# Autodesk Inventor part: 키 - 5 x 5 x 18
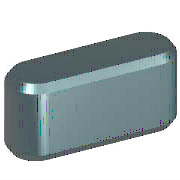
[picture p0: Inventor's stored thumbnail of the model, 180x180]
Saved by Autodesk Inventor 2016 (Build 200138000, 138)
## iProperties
Created: 2012-02
Part Number: 키 - 5 x 5 x 18
Material: 강철, 연강
Description: 키 및 해당 키홈
Document SubType Name: Modeling
Standard: KS B 1311
Designer: mduedu
Standards Organization: KS
Language: ko-KR
Size Designation: 5 x 5 x 18
Categories: <MemberInstance><Categories><Category DisplayName="샤프트 부품" InternalName="7f7aeb1f-a693-4053-b835-cee3144e0d98" Mnemonic="SHFT"><Category DisplayName="키" Interna
Density: 7.86 g/cm^3
Mass: 3.27476 g
Surface Area: 3.57848 cm^2
Volume: 0.416636 cm^3
Appearance: 파란색 - 벽 페인트 - 광택
IsCustomPart: 1
Author: mduedu
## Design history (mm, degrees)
workplane "Work Plane1"
workplane "Work Plane2"
sketch "스케치1"
  geometry: L1 (2.5, 2.5)-(15.5, 2.5); L2 (15.5, -2.5)-(2.5, -2.5); L3 (0, 9.4)-(0, -7.4) reference; L4 (-5, 0)-(30, 0) reference; L5 (18, 0)-(18, 7); A1 r 2.5 centre (2.5, 0) between (2.5, 2.5) and (2.5, -2.5); A2 r 2.5 centre (15.5, 0) between (15.5, -2.5) and (15.5, 2.5)
  constraints: 6 end point, 5 point on circle, 4 tangent, 3 point on line, 2 centre point, 1 horizontal, 1 parallel, 1 perpendicular
  dimensions: "d0" = 2.5 radius of A1 (= 0.5 x PB); "d13" = 2.5 radius of A2 (= 0.5 x PB); "d14" = 18 distance between parallel lines of L5 L3 (= NLG)
extrude "본체1" new body sketch "스케치1" taper "d3" = 0 deg; stored distance "d4" = 10
workplane "Work Plane3"
body "Solid1"
chamfer "모따기1" distance "d8" = 0.4 (= PHH); stored, may be unused: second distance "d9" = 0.4 (= PHH), angle "d15" = 45 deg
other parameters: "d1" = -3 (= -PNT), "d2" = 2 (= PH - PNT), "NLG" = 18 [user parameter; used in 3 equation terms], "PB" = 5 [user parameter; used in 2 equation terms], "PNT" = 3 [user parameter; used in 2 equation terms], "PH" = 5 [user parameter; used in 1 equation term], "PHH" = 0.4 [user parameter; used in 2 equation terms], "d10" = 0, "d16" = 0, "d17" = 0, "d18" = 0, "WDMIN" = 12 [user parameter], "PLB2" = 18 (= NLG) [user parameter], "WDMAX" = 17 [user parameter], "PLB1" = 18 (= NLG) [user parameter], "RR" = 0.16 [user parameter], "PUEB" = 2.3 [user parameter]
